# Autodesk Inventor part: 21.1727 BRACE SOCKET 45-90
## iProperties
Created: 2007-04
Part Number: 21.1727 BRACE SOCKET 45-90
Material: Aluminum-6061
Document SubType Name: Modeling
Designer: Andy Moles
Density: 2.71 g/cm^3
Author: Andy Moles
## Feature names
1. Extrusion1
2. Extrusion2
3. Extrusion3
